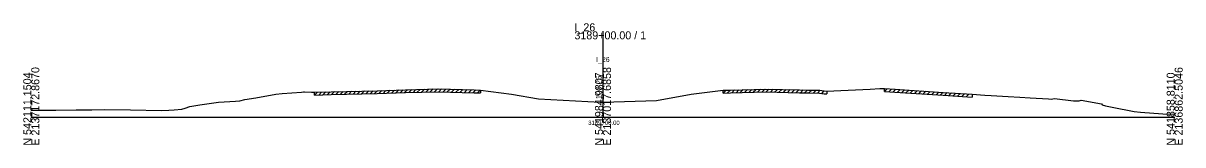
# Model space of a CAD drawing. Extents: x -13101 to 4803, y -924 to 22390.
# Drawn here: x 997.2 to 1402.8, y 14490.3 to 14532.8 of the extents above; entities that cross this region are included whole.
import ezdxf

# ---------------------------------------------------------------- set-up
doc = ezdxf.new("R2010")
doc.units = 0
for name, color, linetype in [('RD_GPK_XS_Cell', 7, 'Continuous'), ('RD_XS_ExGround', 7, 'Continuous'), ('RD_XS_ExPaveRet', 7, 'Continuous'), ('RD_XS_TX_Baseline', 7, 'Continuous'), ('RD_XS_TX_Elev_EX', 7, 'Continuous'), ('RD_XS_TX_Station', 7, 'Continuous')]:
    doc.layers.add(name, color=color, linetype=linetype)

msp = doc.modelspace()

# ---------------------------------------------------------------- linework, layer by layer
at = {"layer": 'RD_GPK_XS_Cell'}
for p, q in [((1200, 14500), (1200, 14529.97)), ((1000, 14500), (1200, 14500)), ((1200, 14500), (1400, 14500))]:
    msp.add_line(p, q, dxfattribs=at)
at = {"layer": 'RD_XS_ExGround'}
msp.add_lwpolyline([(1000, 14502.39), (1002.62, 14502.39), (1005.65, 14502.44), (1008.55, 14502.45), (1015.66, 14502.5), (1021.19, 14502.51), (1025.55, 14502.61), (1034.73, 14502.5), (1045.5, 14502.32), (1048.13, 14502.44), (1049.94, 14502.5), (1052.61, 14502.77), (1053.8, 14503.16), (1055.51, 14503.75), (1058.96, 14504.24), (1065.52, 14505.18), (1071.39, 14505.54), (1072.93, 14505.68), (1074.64, 14506.14), (1078.59, 14506.73), (1085.54, 14508.05), (1087.79, 14508.18), (1094.58, 14508.67), (1095.25, 14508.78), (1095.55, 14508.82), (1098.07, 14508.71), (1098.61, 14508.69), (1099.04, 14508.67), (1104.86, 14508.85), (1120.96, 14509.22), (1130.85, 14509.55), (1142.48, 14509.86), (1154.98, 14509.52), (1157.11, 14509.42), (1167.97, 14507.97), (1177.43, 14506.37), (1186.04, 14505.9), (1199.01, 14505.24), (1200, 14505.26), (1218.74, 14505.76), (1230.88, 14508.05), (1242.04, 14509.35), (1244.59, 14509.46), (1256.91, 14509.78), (1268.71, 14509.51), (1271.88, 14509.42), (1275.72, 14509.38), (1277.42, 14509.17), (1278.25, 14509.1), (1283.22, 14509.3), (1293.41, 14509.75), (1296.88, 14509.99), (1298.5, 14509.93), (1302.15, 14509.74), (1319.02, 14508.62), (1329.1, 14507.96), (1333.56, 14507.64), (1335.78, 14507.48), (1341.71, 14507.15), (1345.79, 14506.91), (1349.46, 14506.72), (1355.8, 14506.33), (1356.78, 14506.31), (1358.01, 14506.44), (1364.6, 14505.64), (1366.59, 14505.65), (1367.33, 14505.92), (1374.42, 14504.64), (1374.58, 14504.31), (1375.82, 14503.88), (1378.07, 14503.49), (1385.83, 14501.99), (1388.04, 14501.73), (1395.81, 14501.18), (1399.69, 14500.96), (1400, 14500.94)], dxfattribs=at)
at = {"layer": 'RD_XS_ExPaveRet'}
for p, q in [((1099.04, 14507.67), (1100.07, 14508.7)), ((1099.04, 14507.67), (1099.04, 14508.67)), ((1099.04, 14507.67), (1104.86, 14507.85)), ((1100.54, 14507.71), (1101.57, 14508.75)), ((1102.04, 14507.76), (1103.07, 14508.79)), ((1103.54, 14507.81), (1104.57, 14508.84)), ((1104.86, 14507.85), (1120.96, 14508.22)), ((1105.04, 14507.85), (1106.06, 14508.88)), ((1106.54, 14507.89), (1107.56, 14508.91)), ((1108.04, 14507.92), (1109.06, 14508.95)), ((1109.54, 14507.96), (1110.56, 14508.98)), ((1111.04, 14507.99), (1112.06, 14509.02)), ((1112.54, 14508.03), (1113.56, 14509.05)), ((1114.04, 14508.06), (1115.06, 14509.09)), ((1115.54, 14508.1), (1116.56, 14509.12)), ((1117.04, 14508.13), (1118.06, 14509.15)), ((1118.54, 14508.17), (1119.56, 14509.19)), ((1120.04, 14508.2), (1121.06, 14509.22)), ((1120.96, 14508.22), (1130.85, 14508.55)), ((1121.54, 14508.24), (1122.57, 14509.28)), ((1123.04, 14508.29), (1124.07, 14509.32)), ((1124.54, 14508.34), (1125.57, 14509.37)), ((1126.04, 14508.39), (1127.07, 14509.42)), ((1127.54, 14508.44), (1128.57, 14509.47)), ((1129.04, 14508.49), (1130.07, 14509.52)), ((1130.54, 14508.54), (1131.57, 14509.57)), ((1130.85, 14508.55), (1142.48, 14508.86)), ((1132.04, 14508.58), (1133.07, 14509.61)), ((1133.54, 14508.62), (1134.57, 14509.65)), ((1135.04, 14508.66), (1136.07, 14509.69)), ((1136.54, 14508.7), (1137.57, 14509.73)), ((1138.04, 14508.74), (1139.07, 14509.77)), ((1139.54, 14508.78), (1140.57, 14509.81)), ((1141.04, 14508.82), (1142.07, 14509.85)), ((1142.48, 14508.86), (1154.98, 14508.52)), ((1142.54, 14508.86), (1143.51, 14509.83)), ((1144.04, 14508.82), (1145.01, 14509.79)), ((1145.54, 14508.78), (1146.51, 14509.75)), ((1147.04, 14508.74), (1148.01, 14509.71)), ((1148.54, 14508.7), (1149.51, 14509.67)), ((1150.04, 14508.66), (1151.01, 14509.63)), ((1151.54, 14508.62), (1152.51, 14509.59)), ((1153.04, 14508.57), (1154.01, 14509.55)), ((1154.54, 14508.53), (1155.5, 14509.5)), ((1154.98, 14508.52), (1157.11, 14508.42)), ((1156.04, 14508.47), (1156.99, 14509.42)), ((1157.11, 14509.42), (1157.11, 14508.42)), ((1242.04, 14508.35), (1243.08, 14509.4)), ((1242.04, 14508.35), (1242.04, 14509.35)), ((1242.04, 14508.35), (1244.59, 14508.46)), ((1243.54, 14508.42), (1244.58, 14509.46)), ((1244.59, 14508.46), (1256.91, 14508.78)), ((1245.04, 14508.48), (1246.06, 14509.5)), ((1246.54, 14508.51), (1247.56, 14509.54)), ((1248.04, 14508.55), (1249.06, 14509.58)), ((1249.54, 14508.59), (1250.56, 14509.62)), ((1251.04, 14508.63), (1252.06, 14509.65)), ((1252.54, 14508.67), (1253.56, 14509.69)), ((1254.04, 14508.7), (1255.06, 14509.73)), ((1255.54, 14508.74), (1256.56, 14509.77)), ((1256.91, 14508.78), (1268.71, 14508.51)), ((1257.04, 14508.77), (1258.02, 14509.75)), ((1258.54, 14508.74), (1259.52, 14509.72)), ((1260.04, 14508.71), (1261.02, 14509.69)), ((1261.54, 14508.67), (1262.52, 14509.65)), ((1263.04, 14508.64), (1264.02, 14509.62)), ((1264.54, 14508.61), (1265.52, 14509.58)), ((1266.04, 14508.57), (1267.02, 14509.55)), ((1267.54, 14508.54), (1268.52, 14509.52)), ((1268.71, 14508.51), (1271.88, 14508.42)), ((1269.04, 14508.5), (1270.01, 14509.48)), ((1270.54, 14508.46), (1271.51, 14509.43)), ((1271.88, 14508.42), (1275.72, 14508.38)), ((1272.04, 14508.42), (1273.03, 14509.41)), ((1273.54, 14508.4), (1274.53, 14509.39)), ((1275.04, 14508.39), (1276, 14509.35)), ((1275.72, 14508.38), (1277.42, 14508.17)), ((1276.54, 14508.28), (1277.43, 14509.17)), ((1277.42, 14508.17), (1278.25, 14508.1)), ((1278.25, 14509.1), (1278.25, 14508.1)), ((1298.5, 14508.93), (1298.5, 14509.93)), ((1298.5, 14508.93), (1299.45, 14509.88)), ((1298.5, 14508.93), (1302.15, 14508.74)), ((1300, 14508.85), (1300.95, 14509.8)), ((1301.5, 14508.77), (1302.45, 14509.72)), ((1302.15, 14508.74), (1319.02, 14507.62)), ((1303, 14508.68), (1303.94, 14509.62)), ((1304.5, 14508.58), (1305.44, 14509.52)), ((1306, 14508.48), (1306.94, 14509.42)), ((1307.5, 14508.38), (1308.44, 14509.32)), ((1309, 14508.29), (1309.94, 14509.22)), ((1310.5, 14508.19), (1311.44, 14509.12)), ((1312, 14508.09), (1312.94, 14509.03)), ((1313.5, 14507.99), (1314.44, 14508.93)), ((1315, 14507.89), (1315.94, 14508.83)), ((1316.5, 14507.79), (1317.44, 14508.73)), ((1318, 14507.69), (1318.94, 14508.63)), ((1319.02, 14507.62), (1329.1, 14506.96)), ((1319.5, 14507.59), (1320.44, 14508.53)), ((1321, 14507.49), (1321.94, 14508.43)), ((1322.5, 14507.4), (1323.44, 14508.33)), ((1324, 14507.3), (1324.94, 14508.24)), ((1325.5, 14507.2), (1326.44, 14508.14)), ((1327, 14507.1), (1327.94, 14508.04)), ((1329.1, 14507.96), (1329.1, 14506.96))]:
    msp.add_line(p, q, dxfattribs=at)

# ---------------------------------------------------------------- texts
at = {"layer": 'RD_GPK_XS_Cell'}
for s, p in [('I_26', (1190, 14529.97)), ('3189+00.00 / 1', (1190, 14527.17))]:
    msp.add_text(s, height=2.8, dxfattribs=at).set_placement(p)
for s, p in [('N 542111.1504', (1000, 14490)), ('E 2137172.8670', (1002.8, 14490)), ('N 541984.9807', (1200, 14490)), ('E 2137017.6858', (1202.8, 14490)), ('N 541858.8110', (1400, 14490)), ('E 2136862.5046', (1402.8, 14490))]:
    msp.add_text(s, height=2.8, rotation=90, dxfattribs=at).set_placement(p)
at = {"layer": 'RD_XS_TX_Baseline'}
msp.add_text('I_26', height=1.75, dxfattribs=at).set_placement((1197.6, 14519.26))
at = {"layer": 'RD_XS_TX_Elev_EX'}
msp.add_text('100.26', height=2, rotation=90, dxfattribs=at).set_placement((1199.5, 14506.26))
at = {"layer": 'RD_XS_TX_Station'}
msp.add_text('3189+00.00', height=1.5, dxfattribs=at).set_placement((1194.83, 14497.26))

doc.saveas('drawing.dxf')
